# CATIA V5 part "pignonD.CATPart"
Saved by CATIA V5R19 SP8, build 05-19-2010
Part number: PignonD
Publications: "Axe", "Appui_1", "Appui_2"
Bounding box of the stored display mesh (mm): x -87.5 to 0, y -30.34 to 30.34, z -30.337 to 30.337
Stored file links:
  G:\EU_thinkMotion\CFAO_2010\MMS_groupe2\MMS_groupe2\OK\melguidj\cfao_elguidj_2AMMSgrB\Modèle 3D\pignonD.CATPart
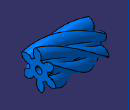
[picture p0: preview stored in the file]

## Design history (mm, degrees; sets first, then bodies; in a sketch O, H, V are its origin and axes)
Parameters
  diametre_primitif = 48.4974 mm {= module_app *z_dent}
  diametre_tete = 62.4974 mm {= diametre_primitif +2*module_normal}
  diametre_pied = 30.9974 mm {= diametre_primitif -2*1.25*module_normal}
  diametre_base = 42 mm {= diametre_primitif *cos(angle_pression )}
  module_normal = 7 mm
  module_app = 8.0829 mm {= module_normal /cos(angle_helice )}
  angle_pression = 30 deg
  angle_helice = 30 deg
  z_dent = 6
  diametre_alesage = -11.0026 mm {= diametre_pied -6*module_normal}
  largeur_denture = 87.5 mm
  pas_helice = 263.8938 mm {= PI *diametre_primitif /tan(angle_helice )}
Set1
  Point1: (0, 0, 0)
  Line1: type PtDir, RefPoint Point1, Direction yz-plane, Start 0, End 20
  Point2: (-5, 0, 24.2487 {= diametre_primitif /2})
  Helix1: Direction Line1, RefPoint Point2, Pitch 263.8938 {= pas_helice}, Height 97.5 {= largeur_denture +10mm}, TaperAngle 0
  Line2: type PtDir, RefPoint Point1, Direction xy-plane, Start 0, End 20
  Plane1: type Normal, Curve Helix1, RefPoint Point2
  Plane2: type Offset, RefPlane yz-plane, Offset 88, reversed
Body1 (main body)
  Sketch1 on yz-plane, origin (0, 0, 0), H (0, 1, 0), V (0, 0, 1)
    circle A1 centre (0, 0) radius 15
    circle A2 centre (0, 0) radius 5.5013
    radius A2 = -5.5013 {= diametre_alesage /2}
    radius A1 = 15
  Pad1: profile Sketch1, direction (1, 0, 0), length 87.5 {= largeur_denture}
  Sketch2 on Plane1, origin (-6.8068, 3.1295, 0), H (-0.5, 0.866, 0), V (0, 0, 1)
    construction circle A1 centre (-3.6136, 0) radius 24.2487
    reference intersected point E1 (-3.6136, 0) from axis of face of Pad1
    reference projected point E2 (-3.6136, 24.2487) from Point2
    construction circle A2 centre (-3.6136, 0) radius 21
    construction line L1 (-3.6136, 24.2487) -> (-3.6136, 0)
    point P2 (-3.6136, 24.2487)
    construction line L2 (-3.6136, 0) -> (-14.1136, 18.1865)
    point P3 (-14.1136, 18.1865)
    arc A3 centre (-14.1136, 18.1865) radius 12.1244 from (-5.778, 9.3821) to (-10.4773, 29.7527) ccw
    point P4 (-3.6136, 24.2487)
    construction line L3 (-3.6136, 0) -> (-9.0644, 23.6281)
    point P5 (-3.6136, 0)
    point P6 (-9.0644, 23.6281)
    arc A4 centre (-2.1417, 20.9484) radius 12.1244 from (-5.778, 9.3821) to (-10.4773, 29.7527) cw
    radius A2 = 21 {= diametre_base /2}
    angle L2 L1 = 30 {= angle_pression}
    angle L3 L1 = 12.9904 {= PI *module_normal /4/(diametre_primitif /2)*1rad}
    concentricity: E1 A1
    coincidence: A1 E2, P2 A1, P3 A2, A3 P4, P4 L1, A3 P2, P5 H, P5 L2, P6 A1
    vertical: L1 V
    symmetry: A4 A3 L3
  Rib1: profile Sketch2, centre curve Helix1
  CircPattern1: of Rib1, instances 6 {= z_dent}, angular step 60 {= 360.0*1 deg/CircPattern1.AngularNumber}, axis from face
  Split1: SplitPlane face
  Split2: SplitPlane face
  Sketch3 on yz-plane, origin (0, 0, 0), H (0, 1, 0), V (0, 0, 1)
    circle A1 centre (0, 0) radius 31.5
    radius A1 = 31.5
  Pocket1: profile Sketch3, direction (1, 0, 0), through (limit type 6), outer side, deactivated
  Sketch4 on yz-plane, origin (0, 0, 0), H (0, 1, 0), V (0, 0, 1)
    circle A1 centre (0, 0) radius 0.6896
    radius A1 = 1.4987 {= diametre_pied/2 -2*module_normal}
  Pocket2: profile Sketch4, direction (1, 0, 0), through (limit type 6), deactivated
  Symmetry1: ToTransfor Pocket2, Reference yz-plane
  Sketch5 on face of Split2, origin (87.5, 0, 0), H (0, 1, 0), V (0, 0, 1)
    circle A1 centre (0, 0) radius 24.2487
    radius A1 = 24.2487 {= diametre_primitif /2}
